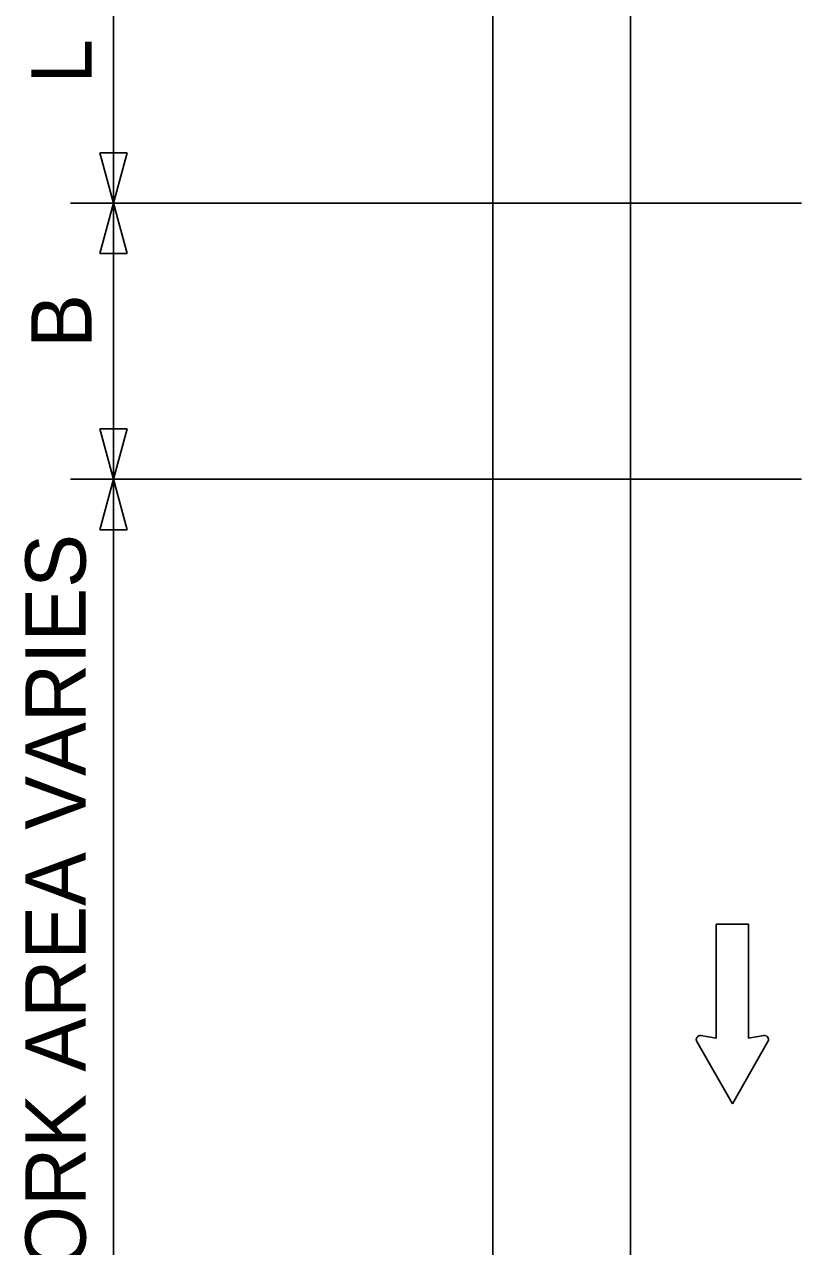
# Model space of a CAD drawing. Extents: x 16731 to 18475, y 5706 to 6928.
# Drawn here: x 16893.1 to 16983.3, y 6459.5 to 6601.4 of the extents above; entities that cross this region are included whole.
import ezdxf

# ---------------------------------------------------------------- set-up
doc = ezdxf.new("R2010")
doc.units = 0
for name, color, linetype in [('MT_SCRATCH_LEVEL_E', 7, 'Continuous'), ('PAVT_EDGE_EX', 7, 'Continuous'), ('TYPICAL_TEXT_DIMEN_PR', 7, 'Continuous')]:
    doc.layers.add(name, color=color, linetype=linetype)

msp = doc.modelspace()

# ---------------------------------------------------------------- linework, layer by layer
at = {"layer": 'MT_SCRATCH_LEVEL_E'}
for p, q in [((16977.1, 6496.95), (16973.36, 6496.95)), ((16973.36, 6496.95), (16973.36, 6483.69)), ((16977.1, 6496.95), (16973.36, 6496.95)), ((16973.36, 6496.95), (16973.36, 6483.69)), ((16977.1, 6483.69), (16977.1, 6496.95)), ((16977.1, 6483.69), (16977.1, 6496.95)), ((16973.36, 6483.69), (16971.58, 6484.01)), ((16973.36, 6483.69), (16971.58, 6484.01)), ((16978.88, 6484.01), (16977.1, 6483.69)), ((16978.88, 6484.01), (16977.1, 6483.69)), ((16971.1, 6483.32), (16975.25, 6476.08)), ((16971.1, 6483.32), (16975.25, 6476.08)), ((16975.25, 6476.08), (16979.36, 6483.32)), ((16975.25, 6476.08), (16979.36, 6483.32))]:
    msp.add_line(p, q, dxfattribs=at)
for centre, start, end in [((16971.51, 6483.55), 80.0362, 209.7731), ((16971.51, 6483.55), 80.0362, 209.7731), ((16978.96, 6483.55), 330.4248, 99.9638), ((16978.96, 6483.55), 330.4248, 99.9638)]:
    msp.add_arc(centre, 0.463, start, end, dxfattribs=at)
at = {"layer": 'PAVT_EDGE_EX'}
for p, q in [((16947.43, 6926.45), (16947.43, 6059.71)), ((16963.43, 6926.45), (16963.43, 6059.71))]:
    msp.add_line(p, q, dxfattribs=at)
at = {"layer": 'TYPICAL_TEXT_DIMEN_PR'}
for p, q in [((16903.43, 6580.67), (16903.43, 6611.2)), ((16903.43, 6580.67), (16901.86, 6586.53)), ((16901.86, 6586.53), (16903.43, 6586.53)), ((16903.43, 6586.53), (16905, 6586.53)), ((16905, 6586.53), (16903.43, 6580.67)), ((16898.43, 6580.67), (16983.26, 6580.67)), ((16901.86, 6574.81), (16903.43, 6580.67)), ((16903.43, 6580.67), (16903.43, 6548.61)), ((16903.43, 6580.67), (16905, 6574.81)), ((16903.43, 6574.81), (16901.86, 6574.81)), ((16905, 6574.81), (16903.43, 6574.81)), ((16903.43, 6548.61), (16901.86, 6554.47)), ((16901.86, 6554.47), (16903.43, 6554.47)), ((16903.43, 6554.47), (16905, 6554.47)), ((16905, 6554.47), (16903.43, 6548.61)), ((16898.43, 6548.61), (16983.26, 6548.61)), ((16903.43, 6548.61), (16901.86, 6542.75)), ((16903.43, 6434.88), (16903.43, 6548.61)), ((16905, 6542.75), (16903.43, 6548.61)), ((16901.86, 6542.75), (16903.43, 6542.75)), ((16903.43, 6542.75), (16905, 6542.75))]:
    msp.add_line(p, q, dxfattribs=at)

# ---------------------------------------------------------------- texts
for s, p in [('L', (16900.88, 6594.54)), ('B', (16900.88, 6563.87)), ('WORK AREA VARIES', (16900.2, 6448.1))]:
    msp.add_text(s, height=7, rotation=90, dxfattribs=at).set_placement(p)

doc.saveas('drawing.dxf')
